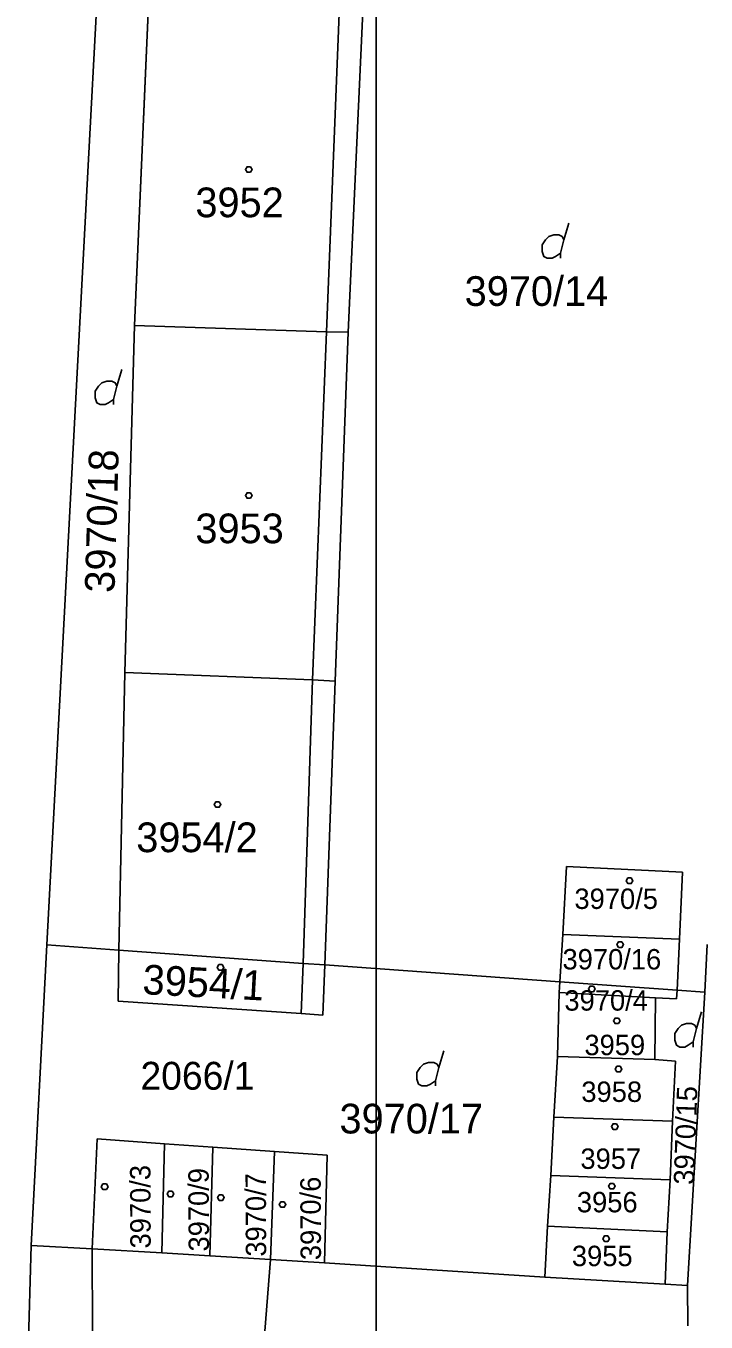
# Model space of a CAD drawing. Extents: x -263587 to -261993, y -1238795 to -1236748.
# Drawn here: x -263010.9 to -262974.3, y -1238078.5 to -1238008.6 of the extents above; entities that cross this region are included whole.
import ezdxf

# ---------------------------------------------------------------- set-up
doc = ezdxf.new("R2010")
doc.units = 0
for name, color, linetype in [('Vrstva 1', 7, 'Continuous'), ('Vrstva 3', 7, 'Continuous'), ('Vrstva 51', 7, 'Continuous')]:
    doc.layers.add(name, color=color, linetype=linetype)

msp = doc.modelspace()

# ---------------------------------------------------------------- linework, layer by layer
at = {"layer": 'Vrstva 1'}
for p, q in [((-263007.54, -1238016.15), (-263006.57, -1237997.98)), ((-263005.04, -1238024.78), (-263004.21, -1238005.82)), ((-263004.21, -1238005.82), (-263005.04, -1238024.78)), ((-262993.96, -1238006.44), (-262994.71, -1238025.11)), ((-262992.69, -1238006.52), (-262993.53, -1238025.14)), ((-262993.53, -1238025.14), (-262992.69, -1238006.52)), ((-263009.77, -1238058.16), (-263007.54, -1238016.15)), ((-262981.92, -1238020.16), (-262981.65, -1238019.26)), ((-263005.56, -1238043.48), (-263005.04, -1238024.78)), ((-263005.04, -1238024.78), (-263005.56, -1238043.48)), ((-263005.04, -1238024.78), (-262994.71, -1238025.11)), ((-262994.71, -1238025.11), (-263005.04, -1238024.78)), ((-262994.71, -1238025.11), (-262995.45, -1238043.87)), ((-262994.71, -1238025.11), (-262993.53, -1238025.14)), ((-262993.53, -1238025.14), (-262994.71, -1238025.11)), ((-262993.53, -1238025.14), (-262994.24, -1238043.95)), ((-262994.24, -1238043.95), (-262993.53, -1238025.14)), ((-263005.99, -1238028.05), (-263005.72, -1238027.15)), ((-263005.89, -1238058.44), (-263005.56, -1238043.48)), ((-263005.56, -1238043.48), (-263005.89, -1238058.44)), ((-262995.45, -1238043.87), (-263005.56, -1238043.48)), ((-263005.56, -1238043.48), (-262995.45, -1238043.87)), ((-262995.45, -1238043.87), (-262995.96, -1238059.16)), ((-262994.24, -1238043.95), (-262995.45, -1238043.87)), ((-262995.45, -1238043.87), (-262994.24, -1238043.95)), ((-262994.24, -1238043.95), (-262994.79, -1238059.24)), ((-262994.79, -1238059.24), (-262994.24, -1238043.95)), ((-262981.98, -1238057.6), (-262981.78, -1238053.94)), ((-262981.78, -1238053.94), (-262981.98, -1238057.6)), ((-262981.78, -1238053.94), (-262975.52, -1238054.23)), ((-262975.52, -1238054.23), (-262981.78, -1238053.94)), ((-262975.52, -1238054.23), (-262975.69, -1238057.84)), ((-262975.69, -1238057.84), (-262975.52, -1238054.23)), ((-262982.13, -1238060.15), (-262981.98, -1238057.6)), ((-262981.98, -1238057.6), (-262982.13, -1238060.15)), ((-262975.69, -1238057.84), (-262981.98, -1238057.6)), ((-262981.98, -1238057.6), (-262975.69, -1238057.84)), ((-263010.6, -1238074.35), (-263009.77, -1238058.16)), ((-263009.77, -1238058.16), (-263005.89, -1238058.44)), ((-263005.89, -1238058.44), (-263009.77, -1238058.16)), ((-262975.69, -1238057.84), (-262975.82, -1238060.6)), ((-262975.82, -1238060.6), (-262975.69, -1238057.84)), ((-262974.32, -1238060.71), (-262974.2, -1238058.14)), ((-262974.2, -1238058.14), (-262974.32, -1238060.71)), ((-263005.92, -1238061.19), (-263005.89, -1238058.44)), ((-263005.89, -1238058.44), (-263005.92, -1238061.19)), ((-262995.96, -1238059.16), (-263005.89, -1238058.44)), ((-263005.89, -1238058.44), (-262995.96, -1238059.16)), ((-262995.96, -1238059.16), (-262996.06, -1238061.86)), ((-262994.79, -1238059.24), (-262995.96, -1238059.16)), ((-262995.96, -1238059.16), (-262994.79, -1238059.24)), ((-262994.79, -1238059.24), (-262994.9, -1238061.95)), ((-262994.9, -1238061.95), (-262994.79, -1238059.24)), ((-262994.79, -1238059.24), (-262982.13, -1238060.15)), ((-262982.13, -1238060.15), (-262994.79, -1238059.24)), ((-262982.17, -1238060.73), (-262982.13, -1238060.15)), ((-262982.13, -1238060.15), (-262982.17, -1238060.73)), ((-262975.82, -1238060.6), (-262982.13, -1238060.15)), ((-262982.13, -1238060.15), (-262975.82, -1238060.6)), ((-262982.26, -1238064.17), (-262982.17, -1238060.73)), ((-262982.17, -1238060.73), (-262982.26, -1238064.17)), ((-262982.17, -1238060.73), (-262976.98, -1238061.01)), ((-262976.98, -1238061.01), (-262982.17, -1238060.73)), ((-262976.98, -1238061.01), (-262977.02, -1238064.34)), ((-262977.02, -1238064.34), (-262976.98, -1238061.01)), ((-262976.98, -1238061.01), (-262975.85, -1238061.07)), ((-262975.85, -1238061.07), (-262976.98, -1238061.01)), ((-262975.85, -1238061.07), (-262975.82, -1238060.6)), ((-262975.82, -1238060.6), (-262975.85, -1238061.07)), ((-262975.82, -1238060.6), (-262974.32, -1238060.71)), ((-262974.32, -1238060.71), (-262975.82, -1238060.6)), ((-262975.26, -1238076.52), (-262974.32, -1238060.71)), ((-262974.32, -1238060.71), (-262975.26, -1238076.52)), ((-262996.06, -1238061.86), (-263005.92, -1238061.19)), ((-263005.92, -1238061.19), (-262996.06, -1238061.86)), ((-262974.78, -1238062.67), (-262974.51, -1238061.77)), ((-262994.9, -1238061.95), (-262996.06, -1238061.86)), ((-262996.06, -1238061.86), (-262994.9, -1238061.95)), ((-262988.66, -1238064.76), (-262988.39, -1238063.86)), ((-262982.45, -1238067.45), (-262982.26, -1238064.17)), ((-262982.26, -1238064.17), (-262982.45, -1238067.45)), ((-262982.26, -1238064.17), (-262977.02, -1238064.34)), ((-262977.02, -1238064.34), (-262982.26, -1238064.17)), ((-262977.02, -1238064.34), (-262975.9, -1238064.42)), ((-262975.9, -1238064.42), (-262977.02, -1238064.34)), ((-262975.9, -1238064.42), (-262976.06, -1238067.66)), ((-262976.06, -1238067.66), (-262975.9, -1238064.42)), ((-262982.62, -1238070.58), (-262982.45, -1238067.45)), ((-262982.45, -1238067.45), (-262982.62, -1238070.58)), ((-262982.45, -1238067.45), (-262976.06, -1238067.66)), ((-262976.06, -1238067.66), (-262982.45, -1238067.45)), ((-262976.06, -1238067.66), (-262976.19, -1238070.81)), ((-262976.19, -1238070.81), (-262976.06, -1238067.66)), ((-263007.33, -1238074.53), (-263007.05, -1238068.61)), ((-263007.05, -1238068.61), (-263007.33, -1238074.53)), ((-263007.05, -1238068.61), (-263003.43, -1238068.87)), ((-263003.43, -1238068.87), (-263007.05, -1238068.61)), ((-263003.58, -1238074.76), (-263003.43, -1238068.87)), ((-263003.43, -1238068.87), (-263003.58, -1238074.76)), ((-263003.43, -1238068.87), (-263000.83, -1238069.05)), ((-263000.83, -1238069.05), (-263003.43, -1238068.87)), ((-263000.83, -1238069.05), (-263000.99, -1238074.92)), ((-263000.99, -1238074.92), (-263000.83, -1238069.05)), ((-263000.83, -1238069.05), (-262997.51, -1238069.29)), ((-262997.51, -1238069.29), (-263000.83, -1238069.05)), ((-262997.51, -1238069.29), (-262997.72, -1238075.12)), ((-262997.72, -1238075.12), (-262997.51, -1238069.29)), ((-262997.51, -1238069.29), (-262994.66, -1238069.49)), ((-262994.66, -1238069.49), (-262997.51, -1238069.29)), ((-262994.66, -1238069.49), (-262994.81, -1238075.3)), ((-262994.81, -1238075.3), (-262994.66, -1238069.49)), ((-262982.8, -1238073.31), (-262982.62, -1238070.58)), ((-262982.62, -1238070.58), (-262982.8, -1238073.31)), ((-262982.62, -1238070.58), (-262976.19, -1238070.81)), ((-262976.19, -1238070.81), (-262982.62, -1238070.58)), ((-262976.19, -1238070.81), (-262976.36, -1238073.63)), ((-262976.36, -1238073.63), (-262976.19, -1238070.81)), ((-262982.94, -1238076.07), (-262982.8, -1238073.31)), ((-262982.8, -1238073.31), (-262982.94, -1238076.07)), ((-262982.8, -1238073.31), (-262976.36, -1238073.63)), ((-262976.36, -1238073.63), (-262982.8, -1238073.31)), ((-262976.36, -1238073.63), (-262976.46, -1238076.44)), ((-262976.46, -1238076.44), (-262976.36, -1238073.63)), ((-263010.89, -1238083.78), (-263010.6, -1238074.35)), ((-263010.6, -1238074.35), (-263007.33, -1238074.53)), ((-263007.33, -1238074.53), (-263010.6, -1238074.35)), ((-263003.58, -1238074.76), (-263007.33, -1238074.53)), ((-263007.33, -1238074.53), (-263003.58, -1238074.76)), ((-263007.33, -1238074.53), (-263007.31, -1238078.96)), ((-263000.99, -1238074.92), (-263003.58, -1238074.76)), ((-263003.58, -1238074.76), (-263000.99, -1238074.92)), ((-262997.72, -1238075.12), (-263000.99, -1238074.92)), ((-263000.99, -1238074.92), (-262997.72, -1238075.12)), ((-262997.72, -1238075.12), (-262998.08, -1238079.66)), ((-262994.81, -1238075.3), (-262997.72, -1238075.12)), ((-262997.72, -1238075.12), (-262994.81, -1238075.3)), ((-262994.81, -1238075.3), (-262982.94, -1238076.07)), ((-262982.94, -1238076.07), (-262994.81, -1238075.3)), ((-262982.94, -1238076.07), (-262976.46, -1238076.44)), ((-262976.46, -1238076.44), (-262982.94, -1238076.07)), ((-262976.46, -1238076.44), (-262975.26, -1238076.52)), ((-262975.26, -1238076.52), (-262976.46, -1238076.44)), ((-262975.26, -1238076.52), (-262975.25, -1238078.69)), ((-262975.25, -1238078.69), (-262975.26, -1238076.52))]:
    msp.add_line(p, q, dxfattribs=at)
for points in [[(-262998.8, -1238016.22), (-262998.71, -1238016.37), (-262998.8, -1238016.52), (-262998.98, -1238016.52), (-262999.07, -1238016.37), (-262998.98, -1238016.22)], [(-262998.8, -1238033.79), (-262998.71, -1238033.94), (-262998.8, -1238034.09), (-262998.98, -1238034.09), (-262999.07, -1238033.94), (-262998.98, -1238033.79)], [(-263000.48, -1238050.44), (-263000.39, -1238050.59), (-263000.48, -1238050.74), (-263000.66, -1238050.74), (-263000.75, -1238050.59), (-263000.66, -1238050.44)], [(-262978.29, -1238054.55), (-262978.2, -1238054.7), (-262978.29, -1238054.85), (-262978.47, -1238054.85), (-262978.56, -1238054.7), (-262978.47, -1238054.55)], [(-262978.79, -1238057.99), (-262978.7, -1238058.14), (-262978.79, -1238058.29), (-262978.97, -1238058.29), (-262979.06, -1238058.14), (-262978.97, -1238057.99)], [(-263000.32, -1238059.22), (-263000.23, -1238059.37), (-263000.32, -1238059.52), (-263000.5, -1238059.52), (-263000.59, -1238059.37), (-263000.5, -1238059.22)], [(-262980.33, -1238060.38), (-262980.24, -1238060.53), (-262980.33, -1238060.68), (-262980.51, -1238060.68), (-262980.6, -1238060.53), (-262980.51, -1238060.38)], [(-262978.98, -1238062.1), (-262978.89, -1238062.25), (-262978.98, -1238062.4), (-262979.16, -1238062.4), (-262979.25, -1238062.25), (-262979.16, -1238062.1)], [(-262978.88, -1238064.7), (-262978.79, -1238064.85), (-262978.88, -1238065), (-262979.06, -1238065), (-262979.15, -1238064.85), (-262979.06, -1238064.7)], [(-262979.09, -1238067.8), (-262979, -1238067.95), (-262979.09, -1238068.1), (-262979.27, -1238068.1), (-262979.36, -1238067.95), (-262979.27, -1238067.8)], [(-263006.56, -1238071.04), (-263006.47, -1238071.19), (-263006.56, -1238071.34), (-263006.74, -1238071.34), (-263006.83, -1238071.19), (-263006.74, -1238071.04)], [(-263003.02, -1238071.43), (-263002.93, -1238071.58), (-263003.02, -1238071.73), (-263003.2, -1238071.73), (-263003.29, -1238071.58), (-263003.2, -1238071.43)], [(-262979.24, -1238071.01), (-262979.15, -1238071.16), (-262979.24, -1238071.31), (-262979.42, -1238071.31), (-262979.51, -1238071.16), (-262979.42, -1238071.01)], [(-263000.3, -1238071.63), (-263000.21, -1238071.78), (-263000.3, -1238071.93), (-263000.48, -1238071.93), (-263000.57, -1238071.78), (-263000.48, -1238071.63)], [(-262996.98, -1238072), (-262996.89, -1238072.15), (-262996.98, -1238072.3), (-262997.16, -1238072.3), (-262997.25, -1238072.15), (-262997.16, -1238072)], [(-262979.55, -1238073.84), (-262979.46, -1238073.99), (-262979.55, -1238074.14), (-262979.73, -1238074.14), (-262979.82, -1238073.99), (-262979.73, -1238073.84)]]:
    msp.add_lwpolyline(points, close=True, dxfattribs=at)
for points in [[(-262982.1, -1238021.15), (-262982.1, -1238020.88), (-262981.92, -1238020.16), (-262982.01, -1238019.98), (-262982.19, -1238019.89), (-262982.46, -1238019.89), (-262982.73, -1238019.98), (-262982.91, -1238020.16), (-262983.09, -1238020.43), (-262983.09, -1238020.79), (-262983, -1238021.06), (-262982.82, -1238021.15), (-262982.55, -1238021.15), (-262982.37, -1238021.06), (-262982.1, -1238020.88)], [(-263006.17, -1238029.04), (-263006.17, -1238028.77), (-263005.99, -1238028.05), (-263006.08, -1238027.87), (-263006.26, -1238027.78), (-263006.53, -1238027.78), (-263006.8, -1238027.87), (-263006.98, -1238028.05), (-263007.16, -1238028.32), (-263007.16, -1238028.68), (-263007.07, -1238028.95), (-263006.89, -1238029.04), (-263006.62, -1238029.04), (-263006.44, -1238028.95), (-263006.17, -1238028.77)], [(-262974.96, -1238063.66), (-262974.96, -1238063.39), (-262974.78, -1238062.67), (-262974.87, -1238062.49), (-262975.05, -1238062.4), (-262975.32, -1238062.4), (-262975.59, -1238062.49), (-262975.77, -1238062.67), (-262975.95, -1238062.94), (-262975.95, -1238063.3), (-262975.86, -1238063.57), (-262975.68, -1238063.66), (-262975.41, -1238063.66), (-262975.23, -1238063.57), (-262974.96, -1238063.39)], [(-262988.84, -1238065.75), (-262988.84, -1238065.48), (-262988.66, -1238064.76), (-262988.75, -1238064.58), (-262988.93, -1238064.49), (-262989.2, -1238064.49), (-262989.47, -1238064.58), (-262989.65, -1238064.76), (-262989.83, -1238065.03), (-262989.83, -1238065.39), (-262989.74, -1238065.66), (-262989.56, -1238065.75), (-262989.29, -1238065.75), (-262989.11, -1238065.66), (-262988.84, -1238065.48)]]:
    msp.add_lwpolyline(points, dxfattribs=at)
at = {"layer": 'Vrstva 3'}
for points in [[(-263003.58, -1238074.76), (-263000.99, -1238074.92), (-262997.72, -1238075.12), (-262994.81, -1238075.3), (-262982.94, -1238076.07), (-262976.46, -1238076.44), (-262975.26, -1238076.52), (-262974.32, -1238060.71), (-262975.82, -1238060.6), (-262982.13, -1238060.15), (-262994.79, -1238059.24), (-262995.96, -1238059.16), (-263005.89, -1238058.44), (-263009.77, -1238058.16), (-263010.6, -1238074.35), (-263007.33, -1238074.53)], [(-263000.99, -1238074.92), (-263003.58, -1238074.76), (-263007.33, -1238074.53), (-263010.6, -1238074.35), (-263009.77, -1238058.16), (-263005.89, -1238058.44), (-262995.96, -1238059.16), (-262994.79, -1238059.24), (-262982.13, -1238060.15), (-262975.82, -1238060.6), (-262974.32, -1238060.71), (-262975.26, -1238076.52), (-262976.46, -1238076.44), (-262982.94, -1238076.07), (-262994.81, -1238075.3), (-262997.72, -1238075.12)]]:
    msp.add_lwpolyline(points, close=True, dxfattribs=at)
at = {"layer": 'Vrstva 51'}
msp.add_lwpolyline([(-262992.03, -1237088.09), (-262695.03, -1237088.09), (-262695.03, -1238768.09), (-262992.03, -1238768.09)], close=True, dxfattribs=at)

# ---------------------------------------------------------------- texts
at = {"layer": 'Vrstva 1'}
for s, height, p in [('3952', 1.6, (-263001.764, -1238018.94)), ('3970/14', 1.6, (-262987.263, -1238023.72)), ('3953', 1.6, (-263001.764, -1238036.51)), ('3954/2', 1.6, (-263004.949, -1238053.16)), ('3970/5', 1.1, (-262981.35, -1238056.22)), ('3970/16', 1.1, (-262981.992, -1238059.48)), ('3970/4', 1.1, (-262981.89, -1238061.7)), ('3959', 1.1, (-262980.811, -1238064.1)), ('3958', 1.1, (-262980.977, -1238066.62)), ('3970/17', 1.6, (-262994.003, -1238068.32)), ('3957', 1.1, (-262981.027, -1238070.23)), ('3956', 1.1, (-262981.217, -1238072.57)), ('3955', 1.1, (-262981.487, -1238075.47))]:
    msp.add_text(s, height=height, dxfattribs=at).set_placement(p)
for s, height, rotation, p in [('3970/18', 1.6, 88.2928, (-263006.123, -1238039.199)), ('3954/1', 1.6, 356.95271, (-263004.64, -1238060.809)), ('3970/15', 1.1, 88.00632, (-262974.907, -1238071.098)), ('3970/3', 1.1, 90.24085, (-263004.168, -1238074.515)), ('3970/9', 1.1, 90.24085, (-263001.028, -1238074.679)), ('3970/7', 1.1, 90.24085, (-262997.948, -1238074.955)), ('3970/6', 1.1, 90.24085, (-262994.998, -1238075.145))]:
    msp.add_text(s, height=height, rotation=rotation, dxfattribs=at).set_placement(p)
at = {"layer": 'Vrstva 3'}
msp.add_text('2066/1', height=1.5, dxfattribs=at).set_placement((-263004.721, -1238065.96))

doc.saveas('drawing.dxf')
